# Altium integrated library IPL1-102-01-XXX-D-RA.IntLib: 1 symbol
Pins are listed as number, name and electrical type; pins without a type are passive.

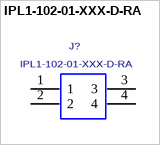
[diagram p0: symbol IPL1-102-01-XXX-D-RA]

## IPL1-102-01-XXX-D-RA
designator J?
Terminal Assembly, Double Row, Right Angle, Thru-Hole, 0.100" x 0.100" Pitch, 4Pins; MANUFACTURER: SAMTEC
footprint IPL1-102-01-XXX-D-RA
pins: 1, 2, 3, 4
